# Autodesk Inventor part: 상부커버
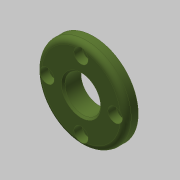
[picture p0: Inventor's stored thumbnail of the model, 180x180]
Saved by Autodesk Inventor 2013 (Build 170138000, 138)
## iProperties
Created: 2019-01
Part Number: 상부커버
Material: 알루미늄 6061
Document SubType Name: Modeling
Designer: mduedu
Density: 2.71 g/cm^3
Mass: 29.8172 g
Surface Area: 54.6428 cm^2
Volume: 11.0026 cm^3
Author: mduedu
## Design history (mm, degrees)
sketch "스케치1"
  geometry: L1 (0, 0)-(7, 0); L2 (7, 0)-(7, 25); L3 (7, 25)-(0, 25); L4 (0, 25)-(0, 0); L5 (7, 0)-(10, 0); L6 (10, 0)-(10, 14); L7 (10, 14)-(7, 14); L8 (7, 14)-(7, 0)
  constraints: 16 end point, 4 parallel, 2 horizontal, 2 perpendicular
  dimensions: "d0" = 50 diameter of L3 L1; "d2" = 10 distance between parallel lines of L6 L4; "d3" = 7 distance of L2.end L3.end; "d4" = 28 diameter of L7 L5
revolve "회전1" sketch "스케치1" stored, may be unused: angle "d5" = 90 deg
sketch "스케치2"
  geometry: C1 r 10 at (0, 0); 1 further point
  constraints: 1 centre point, 1 coincident
  dimensions: "d6" = 20 diameter of C1
extrude "돌출1" cut sketch "스케치2" stored distance "d7" = 10; taper "d8" = 0 deg
chamfer "모따기1" distance "d9" = 1; stored, may be unused: second distance "d10" = 2, angle "d11" = 45 deg
fillet "모깎기1" dims "d12" = 3
sketch "스케치3" dims "d13" = 38
  geometry: 6 further points
  constraints: 2 vertical alignment, 1 coincident, 7 other
  dimensions: "d16" = 360 deg dimension on point (0, 0) point (0, 19) (derived)
chamfer "모따기2" distance "d18" = 1; stored, may be unused: second distance "d19" = 2, angle "d20" = 45 deg
sketch "스케치4"
  geometry: 4 further points
  constraints: 4 other
hole "구멍1" sketch "스케치4" at (-19, 0), (0, -19), (19, 0), (0, 19) diameter "d21" = 4.5; stored, may be unused: countersink angle "d25" = 90 deg, drill point angle "d27" = 0 deg; dims "d22" = 6, "d23" = 8, "d24" = 4.6, "d26" = 8
node "솔리드1"
